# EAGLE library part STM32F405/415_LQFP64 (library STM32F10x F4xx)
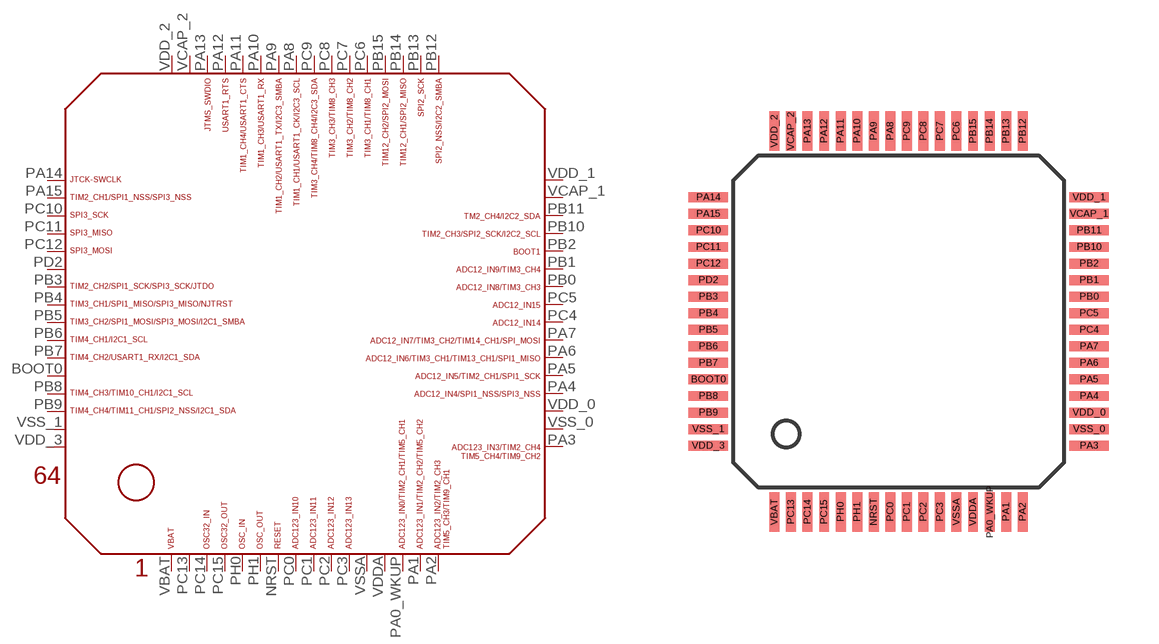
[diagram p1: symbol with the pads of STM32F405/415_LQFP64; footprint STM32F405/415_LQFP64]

Designator prefix -

## STM32F405/415_LQFP64  [STM32F405/415_LQFP64]
BOOT0  BOOT0
NRST  NRST
PA0_WKUP  PA0_AKUP
PA1  PA1
PA2  PA2
PA3  PA3
PA4  PA4
PA5  PA5
PA6  PA6
PA7  PA7
PA8  PA8
PA9  PA9
PA10  PA10
PA11  PA11
PA12  PA12
PA13  PA13
PA14  PA14
PA15  PA15
PB0  PB0
PB1  PB1
PB2  PB2
PB3  PB3
PB4  PB4
PB5  PB5
PB6  PB6
PB7  PB7
PB8  PB8
PB9  PB9
PB10  PB10
PB11  PB11
PB12  PB12
PB13  PB13
PB14  PB14
PB15  PB15
PC0  PC0
PC1  PC1
PC2  PC2
PC3  PC3
PC4  PC4
PC5  PC5
PC6  PC6
PC7  PC7
PC8  PC8
PC9  PC9
PC10  PC10
PC11  PC11
PC12  PC12
PC13  PC13
PC14  PC14
PC15  PC15
PD2  PD2
PH0  PH0
PH1  PH1
VBAT  VBAT
VCAP_1  VCAP_1
VCAP_2  VCAP_2
VDD_0  VDD_0
VDD_1  VDD_1
VDD_2  VDD_2
VDD_3  VDD_3
VDDA  VDDA
VSS_0  VSS_0
VSS_1  VSS_1
VSSA  VSSA

## Footprint STM32F405/415_LQFP64 (pad centres in mm)
smd 1.2 x 0.3: BOOT0 -5.75,-1.75; PA3 5.75,-3.75; PA4 5.75,-2.25; PA5 5.75,-1.75; PA6 5.75,-1.25; PA7 5.75,-0.75; PA14 -5.75,3.75; PA15 -5.75,3.25; PB0 5.75,0.75; PB1 5.75,1.25; PB2 5.75,1.75; PB3 -5.75,0.75; PB4 -5.75,0.25; PB5 -5.75,-0.25; PB6 -5.75,-0.75; PB7 -5.75,-1.25; PB8 -5.75,-2.25; PB9 -5.75,-2.75; PB10 5.75,2.25; PB11 5.75,2.75; PC4 5.75,-0.25; PC5 5.75,0.25; PC10 -5.75,2.75; PC11 -5.75,2.25; PC12 -5.75,1.75; PD2 -5.75,1.25; VCAP_1 5.75,3.25; VDD_0 5.75,-2.75; VDD_1 5.75,3.75; VDD_3 -5.75,-3.75; VSS_0 5.75,-3.25; VSS_1 -5.75,-3.25
smd 0.3 x 1.2: NRST -0.75,-5.75; PA0_WKUP 2.75,-5.75; PA1 3.25,-5.75; PA2 3.75,-5.75; PA8 -0.25,5.75; PA9 -0.75,5.75; PA10 -1.25,5.75; PA11 -1.75,5.75; PA12 -2.25,5.75; PA13 -2.75,5.75; PB12 3.75,5.75; PB13 3.25,5.75; PB14 2.75,5.75; PB15 2.25,5.75; PC0 -0.25,-5.75; PC1 0.25,-5.75; PC2 0.75,-5.75; PC3 1.25,-5.75; PC6 1.75,5.75; PC7 1.25,5.75; PC8 0.75,5.75; PC9 0.25,5.75; PC13 -3.25,-5.75; PC14 -2.75,-5.75; PC15 -2.25,-5.75; PH0 -1.75,-5.75; PH1 -1.25,-5.75; VBAT -3.75,-5.75; VCAP_2 -3.25,5.75; VDD_2 -3.75,5.75; VDDA 2.25,-5.75; VSSA 1.75,-5.75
